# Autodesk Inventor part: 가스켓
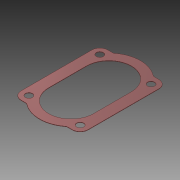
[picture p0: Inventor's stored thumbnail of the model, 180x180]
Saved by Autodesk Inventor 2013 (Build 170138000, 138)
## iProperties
Created: 2023-05
Part Number: 가스켓
Material: 스테인리스강
Document SubType Name: Modeling
Designer: mdu-01
Density: 1 g/cm^3
Author: mdu-01
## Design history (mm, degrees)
sketch "스케치1"
  geometry: L1 (-42.5, 45)-(-42.5, -45) reference; L2 (-32.5, -55)-(-26.325, -55) reference; L3 (26.325, -55)-(32.5, -55) reference; L4 (42.5, -45)-(42.5, 45) reference; L5 (32.5, 55)-(26.325, 55) reference; L6 (-26.325, 55)-(-32.5, 55) reference; L7 (-28.5, -24)-(-28.5, 24) reference; L8 (28.5, 24)-(28.5, -24) reference; C1 r 4.5 at (32.5, -45) reference; C2 r 4.5 at (-32.5, 45) reference; C3 r 4.5 at (32.5, 45) reference; C4 r 4.5 at (-32.5, -45) reference; A1 r 10 centre (-32.5, -45) between (-42.5, -45) and (-32.5, -55) reference; A2 r 3 centre (-26.325, -58) between (-24.488, -55.628) and (-26.325, -55) reference; A3 r 40 centre (0, -24) between (-24.488, -55.628) and (24.488, -55.628) reference; A4 r 3 centre (26.325, -58) between (26.325, -55) and (24.488, -55.628) reference; A5 r 10 centre (32.5, -45) between (32.5, -55) and (42.5, -45) reference; A6 r 10 centre (32.5, 45) between (42.5, 45) and (32.5, 55) reference; A7 r 3 centre (26.325, 58) between (24.488, 55.628) and (26.325, 55) reference; A8 r 40 centre (0, 24) between (24.488, 55.628) and (-24.488, 55.628) reference; A9 r 3 centre (-26.325, 58) between (-26.325, 55) and (-24.488, 55.628) reference; A10 r 10 centre (-32.5, 45) between (-32.5, 55) and (-42.5, 45) reference; A11 r 28.5 centre (0, 24) between (28.5, 24) and (-28.5, 24) reference; A12 r 28.5 centre (0, -24) between (-28.5, -24) and (28.5, -24) reference; 1 further point
extrude "돌출1" new body sketch "스케치1" distance "d0" = 0.5; taper "d1" = 0 deg
node "솔리드1"
node "참조1"
